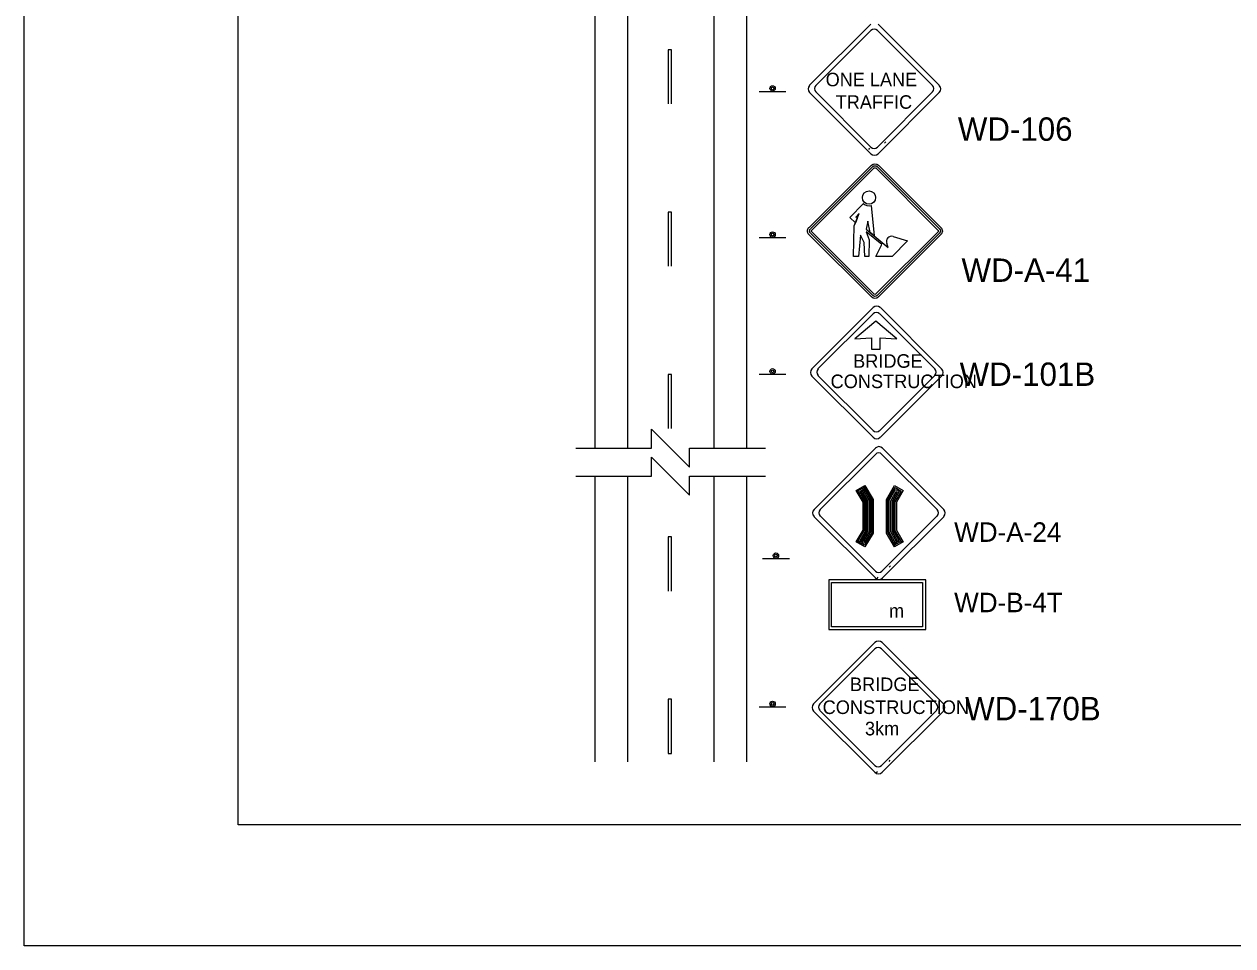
# Model space of a CAD drawing. Extents: x 2170 to 2386, y 134 to 413.
# Drawn here: x 2169.6 to 2277.6, y 133.8 to 216.1 of the extents above; entities that cross this region are included whole.
import ezdxf

# ---------------------------------------------------------------- set-up
doc = ezdxf.new("R2010")
doc.units = 0
for name, color, linetype in [('Level 1', 7, 'Continuous'), ('Level 10', 7, 'Continuous'), ('Level 2', 7, 'Continuous'), ('Level 20', 7, 'Continuous'), ('Level 44', 7, 'Continuous'), ('Level 60', 7, 'Continuous')]:
    doc.layers.add(name, color=color, linetype=linetype)

# ---------------------------------------------------------------- blocks, each defined once
blk = doc.blocks.new('2_95')
at = {"layer": 'Level 1'}
for points in [[(18.2, 120.1), (22.8, 116.1), (17.3, 102.4), (0, 118.7), (41.6, 161.7)], [(18.2, 120.1), (22.8, 116.1), (17.3, 102.4), (0, 118.7), (41.6, 161.7)], [(32.4, 65), (26.3, 0), (11.7, 0), (13.7, 93.4), (17.3, 102.4), (0, 118.7), (41.6, 161.7)], [(65.4, 155.5), (75.1, 62.6), (62.7, 72.8), (55.6, 107.5), (49.8, 83.3), (117.8, 27.3), (113.1, 39.4)], [(65.4, 155.5), (75.1, 62.6), (62.7, 72.8), (55.6, 107.5), (49.8, 83.3), (117.8, 27.3), (113.1, 39.4)], [(65.4, 155.5), (75.1, 62.5), (117.8, 27.3), (113.1, 39.4)], [(132.9, 60.9), (176.6, 47.8), (129.3, 0), (79.5, 0), (98.2, 36), (49.8, 75.6), (59.3, 50.4), (58.1, 0), (46.2, 0), (44, 43), (32.4, 65), (26.3, 0), (11.7, 0), (13.7, 93.4), (28.7, 130.9), (18.2, 120.1)], [(132.9, 60.9), (176.6, 47.8), (129.3, 0), (79.5, 0), (98.2, 36), (49.8, 75.6), (59.3, 50.4), (58.1, 0), (46.2, 0), (44, 43), (32.4, 65), (26.3, 0), (11.7, 0), (13.7, 93.4), (28.7, 130.9), (18.2, 120.1)], [(132.9, 60.9), (176.6, 47.8), (129.3, 0), (79.5, 0), (98.2, 36), (49.8, 75.6), (59.3, 50.4), (58.1, 0), (46.2, 0), (44, 43), (32.4, 65)]]:
    blk.add_lwpolyline(points, dxfattribs=at)
for points in [[(18.2, 120.1), (22.8, 116.1), (28.7, 130.9)], [(62.7, 72.8), (55.6, 107.5), (49.8, 83.3)]]:
    blk.add_lwpolyline(points, close=True, dxfattribs=at)
blk.add_circle((58.9, 179.8), 20.2, dxfattribs=at)
blk.add_circle((58.9, 179.8), 20.2, dxfattribs=at)
blk.add_circle((58.9, 179.8), 20.2, dxfattribs=at)
for centre, radius, start, end in [((58.9, 179.8), 25.1, 226.3135, 284.9576), ((58.9, 179.8), 25.1, 226.3135, 284.9576), ((58.9, 179.8), 25.1, 226.3135, 284.9576), ((128.2, 45.3), 16.3, 73.381, 201.0999), ((128.2, 45.3), 16.3, 73.381, 201.0999), ((128.2, 45.3), 16.3, 73.381, 201.0999)]:
    blk.add_arc(centre, radius, start, end, dxfattribs=at)
blk = doc.blocks.new('WDA41')
at = {"layer": 'Level 1'}
for p, q in [((-6.55, 0.35), (-0.35, 6.54)), ((-6.41, 0.21), (-0.21, 6.4)), ((-6.27, 0.07), (-0.08, 6.27)), ((0.07, 6.27), (6.27, 0.08)), ((0.21, 6.41), (6.41, 0.21)), ((0.35, 6.54), (6.54, 0.35)), ((0.29, 3.83), (0.3, 3.83)), ((-0.35, -6.54), (-6.55, -0.35)), ((-0.21, -6.4), (-6.41, -0.21)), ((-0.07, -6.27), (-6.27, -0.08)), ((6.27, -0.07), (0.08, -6.27)), ((6.41, -0.21), (0.21, -6.4)), ((6.55, -0.35), (0.35, -6.54))]:
    blk.add_line(p, q, dxfattribs=at)
for centre, radius, start, end in [((0, 6.19), 0.495, 45.0349, 135), ((0, 6.19), 0.3, 45.0349, 135), ((0, 6.19), 0.105, 45.0349, 135), ((-6.2, 0), 0.495, 135, 225.0349), ((-6.2, 0), 0.3, 135, 225.0349), ((-6.2, 0), 0.105, 135, 225.0349), ((6.2, 0), 0.105, 315, 45.035), ((6.2, 0), 0.3, 315, 45.035), ((6.2, 0), 0.495, 315, 45.035), ((0, -6.19), 0.495, 225.0348, 315), ((0, -6.19), 0.3, 225.0348, 315), ((0, -6.19), 0.105, 225.0348, 315)]:
    blk.add_arc(centre, radius, start, end, dxfattribs=at)
at = {"layer": 'Level 1', "xscale": 0.032498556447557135, "yscale": -0.032498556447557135, "rotation": 180}
blk.add_blockref('2_95', (2.5, -2.52), dxfattribs=at)
blk = doc.blocks.new('BREAK')
at = {"layer": 'Level 20'}
blk.add_lwpolyline([(-12.499, 0), (-2.5, 0), (-2.5, 2.5), (0, 0), (2.501, -2.501), (2.501, 0), (12.501, 0)], dxfattribs=at)
blk = doc.blocks.new('BR')
at = {"layer": 'Level 20', "xscale": 0.4837996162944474, "yscale": 0.4837996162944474}
blk.add_blockref('BREAK', (1.209, 0), dxfattribs=at)

msp = doc.modelspace()

# ---------------------------------------------------------------- linework, layer by layer
at = {"layer": 'Level 10'}
for p, q in [((2234.19, 178.24), (2234.19, 321.3)), ((2220.64, 178.24), (2220.64, 313.63)), ((2231.29, 178.24), (2231.29, 293.21)), ((2223.55, 178.24), (2223.55, 287.5)), ((2220.64, 150.21), (2220.64, 175.74)), ((2223.55, 150.21), (2223.55, 175.74)), ((2231.29, 150.21), (2231.29, 175.74)), ((2234.19, 150.21), (2234.19, 175.74))]:
    msp.add_line(p, q, dxfattribs=at)
msp.add_lwpolyline([(2241.76, 166.23), (2249.9, 166.23), (2249.9, 162.28), (2241.76, 162.28)], close=True, dxfattribs=at)
at = {"layer": 'Level 2'}
for p, q in [((2227.18, 213.85), (2227.18, 209.02)), ((2227.47, 213.85), (2227.18, 213.85)), ((2227.47, 209.02), (2227.47, 213.85)), ((2246.62, 205.62), (2246.51, 205.52)), ((2245.16, 205.06), (2245.06, 204.95)), ((2227.18, 199.34), (2227.18, 194.5)), ((2227.47, 199.34), (2227.18, 199.34)), ((2227.47, 194.5), (2227.47, 199.34)), ((2227.18, 184.83), (2227.18, 179.99)), ((2227.47, 184.83), (2227.18, 184.83)), ((2227.47, 179.99), (2227.47, 184.83)), ((2227.18, 170.31), (2227.18, 165.47)), ((2227.47, 170.31), (2227.18, 170.31)), ((2227.47, 165.47), (2227.47, 170.31)), ((2247.02, 167.72), (2246.91, 167.61)), ((2245.9, 166.7), (2245.8, 166.6)), ((2227.18, 155.8), (2227.18, 150.96)), ((2227.47, 155.8), (2227.18, 155.8)), ((2227.47, 150.96), (2227.47, 155.8)), ((2227.18, 150.96), (2227.47, 150.96)), ((2246.98, 150.34), (2246.88, 150.24)), ((2245.87, 149.32), (2245.76, 149.22))]:
    msp.add_line(p, q, dxfattribs=at)
at = {"layer": 'Level 44'}
for p, q in [((2245.28, 216.14), (2239.8, 210.68)), ((2251.39, 210.68), (2245.93, 216.14)), ((2240.35, 210.67), (2245.28, 215.59)), ((2245.86, 215.59), (2250.78, 210.67)), ((2235.29, 210.13), (2237.69, 210.13)), ((2239.8, 210.03), (2245.28, 204.55)), ((2239.8, 210.03), (2239.8, 210.03)), ((2245.28, 205.16), (2240.35, 210.09)), ((2250.78, 210.09), (2245.86, 205.16)), ((2245.93, 204.55), (2251.39, 210.03)), ((2235.29, 197.07), (2237.69, 197.07)), ((2245.48, 190.81), (2240, 185.34)), ((2240.55, 185.34), (2245.48, 190.26)), ((2246.07, 190.26), (2250.99, 185.34)), ((2251.6, 185.34), (2246.13, 190.81)), ((2245.72, 189.61), (2243.84, 188.03)), ((2247.61, 188.03), (2245.72, 189.61)), ((2243.84, 188.03), (2245.35, 188.11)), ((2245.35, 188.11), (2245.35, 187.1)), ((2246.1, 187.1), (2246.1, 188.11)), ((2246.1, 188.11), (2247.61, 188.03)), ((2245.35, 187.1), (2246.1, 187.1)), ((2235.29, 184.85), (2237.69, 184.85)), ((2240, 184.69), (2245.48, 179.22)), ((2240.01, 184.69), (2240, 184.69)), ((2245.48, 179.82), (2240.55, 184.75)), ((2250.99, 184.75), (2246.07, 179.82)), ((2246.13, 179.22), (2251.6, 184.69)), ((2245.68, 178.24), (2240.2, 172.77)), ((2251.8, 172.77), (2246.33, 178.24)), ((2240.75, 172.77), (2245.68, 177.69)), ((2246.26, 177.69), (2251.19, 172.77)), ((2240.2, 172.12), (2245.68, 166.65)), ((2240.21, 172.12), (2240.2, 172.12)), ((2245.68, 167.25), (2240.75, 172.18)), ((2251.19, 172.18), (2246.26, 167.25)), ((2246.33, 166.65), (2251.8, 172.12)), ((2235.6, 168.37), (2238, 168.37)), ((2245.64, 160.86), (2240.16, 155.39)), ((2240.71, 155.39), (2245.64, 160.31)), ((2246.22, 160.31), (2251.15, 155.39)), ((2251.76, 155.39), (2246.29, 160.86)), ((2235.29, 155.13), (2237.69, 155.13)), ((2240.16, 154.74), (2245.64, 149.27)), ((2240.17, 154.74), (2240.16, 154.74)), ((2245.64, 149.88), (2240.71, 154.8)), ((2251.15, 154.8), (2246.22, 149.88)), ((2246.29, 149.27), (2251.76, 154.74))]:
    msp.add_line(p, q, dxfattribs=at)
for points in [[(2243.98, 169.86), (2244.58, 170.9), (2244.58, 173.42), (2243.98, 174.46), (2244.75, 174.9), (2245.47, 173.66), (2245.47, 170.66), (2244.75, 169.42), (2243.98, 169.86), (2244.12, 169.89), (2244.69, 170.87), (2244.69, 173.44), (2244.12, 174.42), (2244.71, 174.75), (2245.36, 173.63), (2245.36, 170.68), (2244.7, 169.56), (2244.12, 169.89), (2244.28, 169.94), (2244.8, 170.83), (2244.8, 173.47), (2244.28, 174.38), (2244.67, 174.6), (2245.25, 173.59), (2245.25, 170.72), (2244.67, 169.71), (2244.28, 169.94), (2244.43, 169.97), (2244.91, 170.81), (2244.91, 173.5), (2244.43, 174.33), (2244.63, 174.45), (2245.14, 173.57), (2245.14, 170.75), (2244.62, 169.86), (2244.43, 169.97), (2244.58, 170.02), (2244.68, 169.96), (2244.58, 170.02), (2245.02, 170.78), (2245.02, 173.53), (2244.58, 174.29), (2244.68, 174.35), (2244.75, 174.9)], [(2247.39, 169.42), (2246.67, 170.66), (2246.67, 173.66), (2247.39, 174.9), (2248.16, 174.46), (2247.56, 173.42), (2247.56, 170.9), (2248.16, 169.86), (2247.39, 169.42), (2247.43, 169.59), (2246.8, 170.69), (2246.8, 173.62), (2247.44, 174.72), (2247.99, 174.4), (2247.43, 173.45), (2247.43, 170.86), (2247.99, 169.91), (2247.43, 169.59), (2247.48, 169.76), (2246.92, 170.72), (2246.92, 173.59), (2247.49, 174.55), (2247.81, 174.36), (2247.31, 173.48), (2247.31, 170.83), (2247.81, 169.95), (2247.48, 169.76), (2247.53, 169.93), (2247.06, 170.76), (2247.06, 173.55), (2247.53, 174.38), (2247.64, 174.31), (2247.17, 173.52), (2247.18, 170.79), (2247.64, 170), (2247.53, 169.93), (2248.16, 169.86)]]:
    msp.add_lwpolyline(points, dxfattribs=at)
msp.add_lwpolyline([(2250.18, 166.46), (2241.51, 166.46), (2241.51, 162.04), (2250.18, 162.04)], close=True, dxfattribs=at)
for centre, radius in [((2236.5, 210.4), 0.24), ((2236.5, 210.4), 0.12), ((2236.5, 197.34), 0.24), ((2236.5, 197.34), 0.12), ((2236.5, 185.11), 0.24), ((2236.5, 185.11), 0.12), ((2236.8, 168.64), 0.24), ((2236.8, 168.64), 0.12), ((2236.5, 155.39), 0.24), ((2236.5, 155.39), 0.12)]:
    msp.add_circle(centre, radius, dxfattribs=at)
for centre, radius, start, end in [((2245.57, 215.3), 0.412, 45, 135), ((2240.13, 210.35), 0.458, 135, 225), ((2240.64, 210.38), 0.412, 135, 225), ((2250.49, 210.38), 0.412, 315, 45), ((2251.07, 210.35), 0.458, 315, 45), ((2245.57, 205.45), 0.412, 225, 315), ((2245.6, 204.88), 0.458, 225, 315), ((2245.8, 190.49), 0.458, 45, 135), ((2245.77, 189.97), 0.412, 45, 135), ((2240.33, 185.01), 0.458, 135, 225), ((2240.85, 185.04), 0.412, 135, 225), ((2250.7, 185.04), 0.412, 315, 45), ((2251.28, 185.01), 0.458, 315, 45), ((2245.77, 180.12), 0.412, 225, 315), ((2245.8, 179.54), 0.458, 225, 315), ((2246, 177.92), 0.458, 45, 135), ((2245.97, 177.4), 0.412, 45, 135), ((2240.53, 172.45), 0.458, 135, 225), ((2241.04, 172.47), 0.412, 135, 225), ((2250.9, 172.47), 0.412, 315, 45), ((2251.47, 172.45), 0.458, 315, 45), ((2245.97, 167.55), 0.412, 225, 315), ((2246, 166.97), 0.458, 225, 315), ((2245.96, 160.54), 0.458, 45, 135), ((2245.93, 160.02), 0.412, 45, 135), ((2240.49, 155.07), 0.458, 135, 225), ((2241.01, 155.1), 0.412, 135, 225), ((2250.86, 155.1), 0.412, 315, 45), ((2251.44, 155.07), 0.458, 315, 45), ((2245.93, 150.17), 0.412, 225, 315), ((2245.96, 149.6), 0.458, 225, 315)]:
    msp.add_arc(centre, radius, start, end, dxfattribs=at)
at = {"layer": 'Level 60'}
for points in [[(2169.62, 412.76), (2385.62, 412.76), (2385.62, 133.76), (2169.62, 133.76)], [(2188.75, 401.95), (2375.62, 401.95), (2375.62, 144.57), (2188.75, 144.57)]]:
    msp.add_lwpolyline(points, close=True, dxfattribs=at)

# ---------------------------------------------------------------- block references
at = {"layer": 'Level 1', "xscale": 0.9, "yscale": -0.9, "rotation": 180}
msp.add_blockref('WDA41', (2245.64, 197.65), dxfattribs=at)
at = {"layer": 'Level 20', "xscale": 1.4, "yscale": 1.4}
for p in [(2225.69, 178.24), (2225.69, 175.74)]:
    msp.add_blockref('BR', p, dxfattribs=at)

# ---------------------------------------------------------------- texts
at = {"layer": 'Level 10'}
for s, height, p in [('ONE LANE', 1.209, (2241.24, 210.59)), ('TRAFFIC', 1.209, (2242.14, 208.58)), ('WD-106', 2.09, (2253.05, 205.72)), ('WD-A-41', 2.09, (2253.38, 193.11)), ('WD-101B', 2.09, (2253.21, 183.81)), ('WD-A-24', 1.742, (2252.72, 169.87)), ('WD-B-4T', 1.742, (2252.72, 163.58)), ('WD-170B', 2.09, (2253.7, 153.92))]:
    msp.add_text(s, height=height, dxfattribs=at).set_placement(p)
at = {"layer": 'Level 44'}
for s, p in [('BRIDGE', (2243.69, 185.43)), ('CONSTRUCTION', (2241.68, 183.61)), ('BRIDGE', (2243.41, 156.53))]:
    msp.add_text(s, height=1.214, rotation=360, dxfattribs=at).set_placement(p)
for s, height, p in [('m', 1.21, (2246.9, 163.1)), ('CONSTRUCTION', 1.2143, (2240.97, 154.48)), ('3km', 1.214, (2244.75, 152.57))]:
    msp.add_text(s, height=height, dxfattribs=at).set_placement(p)

doc.saveas('drawing.dxf')
